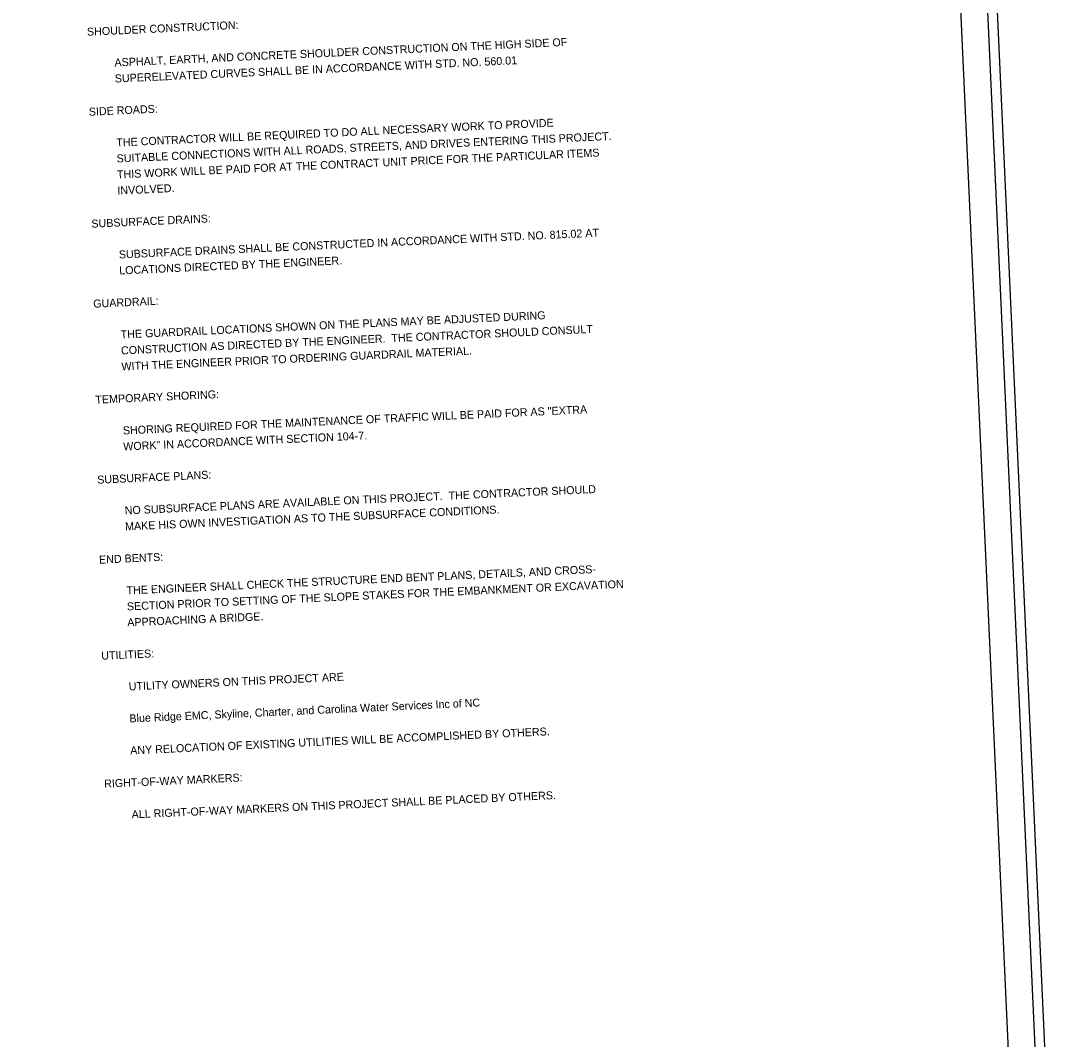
# Model space of a CAD drawing. Extents: x 1190067 to 1192950, y 891516 to 893460.
# Drawn here: x 1191613.6 to 1191806, y 892043.5 to 892232.8 of the extents above; entities that cross this region are included whole.
import ezdxf

# ---------------------------------------------------------------- set-up
doc = ezdxf.new("R2010")
doc.units = 0
for name, color, linetype in [('Sheet Data Text CELL', 7, 'Continuous'), ('Sheet Plan CELL', 7, 'Continuous'), ('Sheet Plot Border Inside CELL', 7, 'Continuous'), ('Sheet Plot Border Outside CELL', 7, 'Continuous')]:
    doc.layers.add(name, color=color, linetype=linetype)

msp = doc.modelspace()

# ---------------------------------------------------------------- linework, layer by layer
at = {"layer": 'Sheet Plan CELL'}
msp.add_lwpolyline([(1191779.6, 892424.42), (1191180.22, 892397), (1191199.42, 891977.44), (1191798.79, 892004.86)], close=True, dxfattribs=at)
at = {"layer": 'Sheet Plot Border Inside CELL'}
msp.add_lwpolyline([(1191138.13, 891973.63), (1191803.83, 892004.09), (1191784.54, 892425.65), (1191118.84, 892395.19)], close=True, dxfattribs=at)
at = {"layer": 'Sheet Plot Border Outside CELL'}
msp.add_lwpolyline([(1191133.3, 891965.4), (1191805.99, 891996.18), (1191785.98, 892433.72), (1191113.28, 892402.94)], close=True, dxfattribs=at)

# ---------------------------------------------------------------- texts
at = {"layer": 'Sheet Data Text CELL'}
for s, p in [('SHOULDER CONSTRUCTION:  ', (1191625.95, 892229.98)), ('         ASPHALT, EARTH, AND CONCRETE SHOULDER CONSTRUCTION ON THE HIGH SIDE OF', (1191626.09, 892224.04)), ('         SUPERELEVATED CURVES SHALL BE IN ACCORDANCE WITH STD. NO. 560.01', (1191626.15, 892221.06)), ('SIDE ROADS:  ', (1191626.29, 892215.12)), ('         THE CONTRACTOR WILL BE REQUIRED TO DO ALL NECESSARY WORK TO PROVIDE ', (1191626.43, 892209.17)), ('         SUITABLE CONNECTIONS WITH ALL ROADS, STREETS, AND DRIVES ENTERING THIS PROJECT.  ', (1191626.49, 892206.2)), ('         THIS WORK WILL BE PAID FOR AT THE CONTRACT UNIT PRICE FOR THE PARTICULAR ITEMS ', (1191626.56, 892203.23)), ('         INVOLVED.  ', (1191626.63, 892200.25)), ('SUBSURFACE DRAINS:', (1191626.77, 892194.31)), ('         SUBSURFACE DRAINS SHALL BE CONSTRUCTED IN ACCORDANCE WITH STD. NO. 815.02 AT ', (1191626.9, 892188.36)), ('         LOCATIONS DIRECTED BY THE ENGINEER.  ', (1191626.97, 892185.39)), ('GUARDRAIL:  ', (1191627.11, 892179.45)), ('         THE GUARDRAIL LOCATIONS SHOWN ON THE PLANS MAY BE ADJUSTED DURING ', (1191627.24, 892173.5)), ('         CONSTRUCTION AS DIRECTED BY THE ENGINEER.  THE CONTRACTOR SHOULD CONSULT', (1191627.31, 892170.53)), ('         WITH THE ENGINEER PRIOR TO ORDERING GUARDRAIL MATERIAL.', (1191627.38, 892167.55)), ('TEMPORARY SHORING:  ', (1191627.51, 892161.61)), ('         SHORING REQUIRED FOR THE MAINTENANCE OF TRAFFIC WILL BE PAID FOR AS "EXTRA ', (1191627.65, 892155.66)), ('         WORK" IN ACCORDANCE WITH SECTION 104-7.  ', (1191627.72, 892152.69)), ('SUBSURFACE PLANS:  ', (1191627.85, 892146.74)), ('         NO SUBSURFACE PLANS ARE AVAILABLE ON THIS PROJECT.  THE CONTRACTOR SHOULD ', (1191627.99, 892140.8)), ('         MAKE HIS OWN INVESTIGATION AS TO THE SUBSURFACE CONDITIONS.  ', (1191628.06, 892137.83)), ('END BENTS:  ', (1191628.19, 892131.88)), ('         THE ENGINEER SHALL CHECK THE STRUCTURE END BENT PLANS, DETAILS, AND CROSS-', (1191628.33, 892125.94)), ('         SECTION PRIOR TO SETTING OF THE SLOPE STAKES FOR THE EMBANKMENT OR EXCAVATION ', (1191628.4, 892122.96)), ('         APPROACHING A BRIDGE.  ', (1191628.47, 892119.99)), ('UTILITIES:  ', (1191628.6, 892114.04)), ('         UTILITY OWNERS ON THIS PROJECT ARE  ', (1191628.74, 892108.1)), ('         Blue Ridge EMC, Skyline, Charter, and Carolina Water Services Inc of NC', (1191628.87, 892102.15)), ('         ANY RELOCATION OF EXISTING UTILITIES WILL BE ACCOMPLISHED BY OTHERS.  ', (1191629.01, 892096.21)), ('RIGHT-OF-WAY MARKERS:  ', (1191629.14, 892090.26)), ('         ALL RIGHT-OF-WAY MARKERS ON THIS PROJECT SHALL BE PLACED BY OTHERS.  ', (1191629.28, 892084.32))]:
    msp.add_text(s, height=1.4872, rotation=2.6195, dxfattribs=at).set_placement(p)

doc.saveas('drawing.dxf')
